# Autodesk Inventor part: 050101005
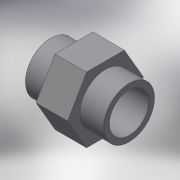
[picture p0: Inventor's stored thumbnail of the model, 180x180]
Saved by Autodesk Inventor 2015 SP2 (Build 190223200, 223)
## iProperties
Created: 2017-10
Part Number: 050101005
Material: Generic
Description: PLASSON THREADED SOCKET PVC 1/2"
Document SubType Name: Modeling
Designer: KIM
Density: 1 g/cm^3
Appearance: Default
Author: KIM
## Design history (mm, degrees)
derived "050101.ipt"
feature "Solid1::050101.ipt"
tag "TaggingFeature1"
body "Solid1"
other parameters: "d0" = 36, "d1" = 18.631, "d3" = 18.631, "d4" = 16.7679, "d5" = 17, "d6" = 17, "d7" = 24.2203, "d8" = 24.2203, "d10" = 11.9, "d13" = 0, "d14" = 0.18631, "d15" = 12, "G_" = 18.631, "B_" = 12, "lt_" = 17, "H_" = 36
